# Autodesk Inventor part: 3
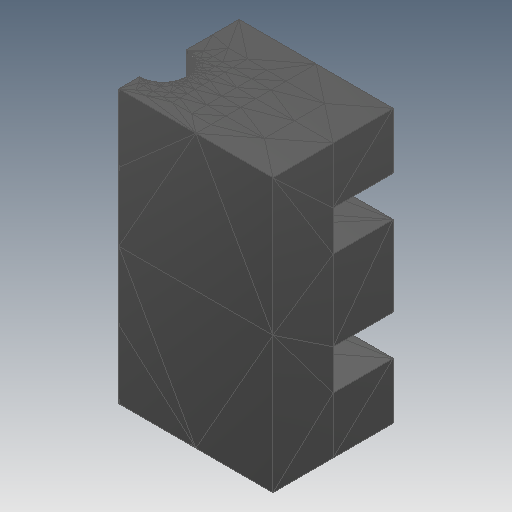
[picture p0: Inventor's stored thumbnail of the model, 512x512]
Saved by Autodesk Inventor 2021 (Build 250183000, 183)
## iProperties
Created: 2026-04
Part Number: 3
Material: Generic
Document SubType Name: Modeling
Designer: JCBG
Density: 1 g/cm^3
Appearance: Default
Author: JCBG
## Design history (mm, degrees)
node "3"
  node "MeshFeature1"
